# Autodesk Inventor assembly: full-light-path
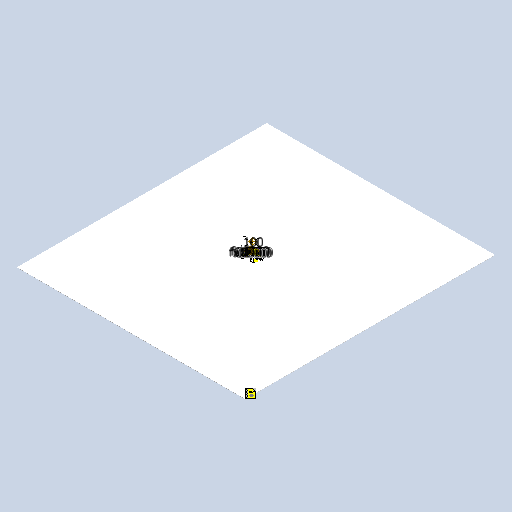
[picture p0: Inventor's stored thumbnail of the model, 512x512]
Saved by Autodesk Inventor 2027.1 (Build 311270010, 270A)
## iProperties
Created: 2026-07
Part Number: full-light-path
Document SubType Name: Assembly
Designer: dunge
Author: dunge
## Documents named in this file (29)
- C:\Users\dunge\OneDrive\Documents\Inventor\Inventor\Inventor\simplified-drawings\full-light-path.iam
- C:\Users\dunge\OneDrive\Documents\Inventor\Inventor\Inventor\simplified-drawings\master-beam.ipt
- C:\Users\dunge\OneDrive\Documents\Inventor\Inventor\Inventor\simplified-drawings\lens.ipt
- C:\Users\dunge\OneDrive\Documents\Inventor\Inventor\Inventor\simplified-drawings\imports\N16XLWD-PF-Solidworks\N16XLWD-PF-Solidworks.ipt
- C:\Users\dunge\OneDrive\Documents\Inventor\Inventor\Inventor\simplified-drawings\imports\M470L5-Solidworks\M470L5-Solidworks.ipt
- C:\Users\dunge\OneDrive\Documents\Inventor\Inventor\Inventor\simplified-drawings\imports\DM97-15-005.ipt
- C:\Users\dunge\OneDrive\Documents\Inventor\Inventor\Inventor\simplified-drawings\simple-side-dm.ipt
- C:\Users\dunge\OneDrive\Documents\Inventor\Inventor\Inventor\simplified-drawings\chopper-simple.ipt
- C:\Users\dunge\OneDrive\Documents\Inventor\Inventor\Inventor\simplified-drawings\electro-optic-modulator-eom-simple.ipt
- C:\Users\dunge\OneDrive\Documents\Inventor\Inventor\Inventor\simplified-drawings\fs-laser-simple.ipt
- C:\Users\dunge\OneDrive\Documents\Inventor\Inventor\Inventor\simplified-drawings\imports\quarter-wave-plate-qwp-simple.ipt
- C:\Users\dunge\OneDrive\Documents\Inventor\Inventor\Inventor\simplified-drawings\imports\polarizing-beam-splitter-pbs-simple.ipt
- C:\Users\dunge\OneDrive\Documents\Inventor\Inventor\Inventor\simplified-drawings\imports\galvo-mirrors-simple.ipt
- C:\Users\dunge\OneDrive\Documents\Inventor\Inventor\Inventor\simplified-drawings\imports\photomultiplier-tube-pmt-simple.ipt
- C:\Users\dunge\OneDrive\Documents\Inventor\Inventor\Inventor\simplified-drawings\scaled-scmos-camera.ipt
- C:\Users\dunge\OneDrive\Documents\Inventor\Inventor\Inventor\simplified-drawings\galvo-assembly-simple.iam
- C:\Users\dunge\OneDrive\Documents\Inventor\Inventor\Inventor\simplified-drawings\camera-aligner.ipt
- C:\Users\dunge\OneDrive\Documents\Inventor\Inventor\Inventor\simplified-drawings\excitation-filter-simple.ipt
- C:\Users\dunge\OneDrive\Documents\Inventor\Inventor\Inventor\simplified-drawings\emission-filter-simple.ipt
- C:\Users\dunge\OneDrive\Documents\Inventor\Inventor\Inventor\simplified-drawings\imports\D25S-Step\D25S-Step.ipt
- C:\Users\dunge\OneDrive\Documents\Inventor\Inventor\Inventor\simplified-drawings\scan-lens-sl-simple\scan-lens.ipt
- C:\Users\dunge\OneDrive\Documents\Inventor\Inventor\Inventor\simplified-drawings\scan-lens-sl-simple.ipt
- C:\Users\dunge\OneDrive\Documents\Inventor\Inventor\Inventor\simplified-drawings\scan-lens-sl-simple\tube-lens.ipt
- C:\Users\dunge\OneDrive\Documents\Inventor\Inventor\Inventor\simplified-drawings\polarizing-beam-splitter-pmt-small-simple.ipt
- C:\Users\dunge\OneDrive\Documents\Inventor\Inventor\Inventor\simplified-drawings\wave-plate.ipt
- C:\Users\dunge\OneDrive\Documents\Inventor\Inventor\Inventor\simplified-drawings\pmt-filter.ipt
- C:\Users\dunge\OneDrive\Documents\Inventor\Inventor\Inventor\simplified-drawings\lens\lens-02.ipt
- C:\Users\dunge\OneDrive\Documents\Inventor\Inventor\Inventor\simplified-drawings\lens\lens-03.ipt
- C:\Users\dunge\OneDrive\Documents\Inventor\Inventor\Inventor\simplified-drawings\lens\lens-04.ipt
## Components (43 placed, 27 different names)
1. master-beam:1
2. N16XLWD-PF-Solidworks:1 — Mate:3, Mate:4
3. M470L5-Solidworks:1 — Mate:5, Mate:6
4. DM97-15-005:1 — Mate:11, Mate:12, Angle:1
5. simple-side-dm:1 — Mate:103, Mate:104, Flush:6
6. simple-side-dm:2 — Mate:21, Mate:22, Flush:7
7. simple-side-dm:3 — Mate:23, Mate:24
8. chopper-simple:1 — Mate:25, Mate:26
9. electro-optic-modulator-eom-simple:1 — Mate:109, Mate:110
10. fs-laser-simple:1 — Angle:2, Mate:111, Mate:112
11. quarter-wave-plate-qwp-simple:1 — Mate:48, Mate:49
12. polarizing-beam-splitter-pbs-simple:1 — Mate:50, Mate:51
13. galvo-mirrors-simple:1
14. lens:11 — Mate:53, Mate:56
15. lens:13 — Mate:55, Mate:58
16. lens:15 — Mate:65, Mate:67
17. lens:16 — Mate:66, Mate:68
18. photomultiplier-tube-pmt-simple:1 — Mate:69, Mate:70
19. scaled-scmos-camera:1 — Mate:71, Mate:72, Angle:3
20. galvo-assembly-simple:1 [sub-assembly] — Mate:76, Mate:101, Mate:102, Flush:4, Flush:5
21. camera-aligner:1 — Flush:1, Flush:2, Flush:3
22. excitation-filter-simple:1 — Mate:77, Mate:78
23. emission-filter-simple:1 — Mate:81, Mate:82
24. D25S-Step:1 — Mate:83, Mate:84
25. scan-lens:1
26. tube-lens:2
27. polarizing-beam-splitter-pmt-small-simple:1 — Angle:4, Mate:105, Mate:106
28. wave-plate:1 — Mate:91, Mate:92
29. wave-plate:2 — Mate:93, Mate:96
30. wave-plate:3 — Mate:94, Mate:95
31. wave-plate:4 — Mate:107, Mate:108
32. pmt-filter:1 — Mate:99, Mate:100
33. lens-02:17 — Mate:114, Mate:117
34. lens-03:18 — Mate:113, Mate:118
35. lens-02:19 — Mate:115, Mate:119
36. lens-03:20 — Mate:116, Mate:120
37. lens-03:21 — Mate:127, Mate:128
38. lens-03:22 — Mate:125, Mate:126
39. lens-02:23 — Mate:123, Mate:124
40. lens-02:24 — Mate:121, Mate:122
41. lens-02:25 — Mate:129, Mate:130
42. lens-02:26 — Mate:131, Mate:132
43. lens-04:28 — Mate:133, Mate:134
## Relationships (88: Mate 77, Flush 7, Angle 4)
- Mate:3: N16XLWD-PF-Solidworks:1
- Mate:4: N16XLWD-PF-Solidworks:1
- Mate:5: M470L5-Solidworks:1
- Mate:6: M470L5-Solidworks:1
- Mate:11: DM97-15-005:1
- Mate:12: DM97-15-005:1
- Angle:1: DM97-15-005:1
- Mate:21: simple-side-dm:2
- Mate:22: simple-side-dm:2
- Mate:23: simple-side-dm:3
- Mate:24: simple-side-dm:3
- Mate:25: chopper-simple:1
- Mate:26: chopper-simple:1
- Mate:48: quarter-wave-plate-qwp-simple:1
- Mate:49: quarter-wave-plate-qwp-simple:1
- Mate:50: polarizing-beam-splitter-pbs-simple:1
- Mate:51: polarizing-beam-splitter-pbs-simple:1
- Mate:53: lens:11
- Mate:55: lens:13
- Mate:56: lens:11
- Mate:58: lens:13
- Mate:65: lens:15
- Mate:66: lens:16
- Mate:67: lens:15
- Mate:68: lens:16
- Mate:69: photomultiplier-tube-pmt-simple:1
- Mate:70: photomultiplier-tube-pmt-simple:1
- Mate:71: scaled-scmos-camera:1
- Mate:72: scaled-scmos-camera:1
- Mate:76: galvo-assembly-simple:1
- Flush:1: camera-aligner:1
- Flush:2: camera-aligner:1
- Flush:3: camera-aligner:1
- Mate:77: excitation-filter-simple:1
- Mate:78: excitation-filter-simple:1
- Mate:81: emission-filter-simple:1
- Mate:82: emission-filter-simple:1
- Mate:83: D25S-Step:1
- Mate:84: D25S-Step:1
- Angle:2: fs-laser-simple:1
- Angle:3: scaled-scmos-camera:1
- Angle:4: polarizing-beam-splitter-pmt-small-simple:1
- Mate:91: wave-plate:1
- Mate:92: wave-plate:1
- Mate:93: wave-plate:2
- Mate:94: wave-plate:3
- Mate:95: wave-plate:3
- Mate:96: wave-plate:2
- Mate:99: pmt-filter:1
- Mate:100: pmt-filter:1
- Mate:101: galvo-assembly-simple:1
- Mate:102: galvo-assembly-simple:1
- Mate:103: simple-side-dm:1
- Mate:104: simple-side-dm:1
- Mate:105: polarizing-beam-splitter-pmt-small-simple:1
- Mate:106: polarizing-beam-splitter-pmt-small-simple:1
- Mate:107: wave-plate:4
- Mate:108: wave-plate:4
- Mate:109: electro-optic-modulator-eom-simple:1
- Mate:110: electro-optic-modulator-eom-simple:1
- Mate:111: fs-laser-simple:1
- Mate:112: fs-laser-simple:1
- Mate:113: lens-03:18
- Mate:114: lens-02:17
- Mate:115: lens-02:19
- Mate:116: lens-03:20
- Mate:117: lens-02:17
- Mate:118: lens-03:18
- Mate:119: lens-02:19
- Mate:120: lens-03:20
- Mate:121: lens-02:24
- Mate:122: lens-02:24
- Mate:123: lens-02:23
- Mate:124: lens-02:23
- Mate:125: lens-03:22
- Mate:126: lens-03:22
- Mate:127: lens-03:21
- Mate:128: lens-03:21
- Mate:129: lens-02:25
- Mate:130: lens-02:25
- Mate:131: lens-02:26
- Mate:132: lens-02:26
- Mate:133: lens-04:28
- Mate:134: lens-04:28
- Flush:4: galvo-assembly-simple:1
- Flush:5: galvo-assembly-simple:1
- Flush:6: simple-side-dm:1
- Flush:7: simple-side-dm:2
## Named parameters: Finish10_Area = 1956.76338 mm, Finish1_Area = 4606.70953 mm, Finish2_Area = 3690.95683 mm, Finish3_Area = 1555.33941 mm, Finish6_Area = 1189.9374 mm, Finish7_Area = 7.26557e+07 mm, Finish8_Area = 902.78555 mm, Finish9_Area = 4402.8649 mm
